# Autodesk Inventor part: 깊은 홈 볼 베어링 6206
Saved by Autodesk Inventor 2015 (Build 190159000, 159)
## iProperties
Created: 2026-07
Part Number: 깊은 홈 볼 베어링 6206
Material: 일반
Document SubType Name: Modeling
Designer: user
Density: 1 g/cm^3
Appearance: 기본값
Author: user
Author: jhkim
Description: 깊은 그루브 볼 베어링
Creation Date: 2026-07-01
Sending System: Autodesk Inventor 2027
Preprocessor: ST-DEVELOPER v20.1
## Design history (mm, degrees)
node "깊은 홈 볼 베어링 62061"
body "Solid1"
node "Solid1_1"
node "Solid1_2"
node "Solid1_3"
node "Solid1_4"
node "Solid1_5"
node "Solid1_6"
node "Solid1_7"
node "Solid1_8"
node "Solid1_9"
node "Solid1_10"
node "기준1"
node "기준2"
node "기준3"
node "기준4"
node "기준5"
node "기준6"
node "기준7"
node "기준8"
node "기준9"
node "기준10"
node "기준11"
